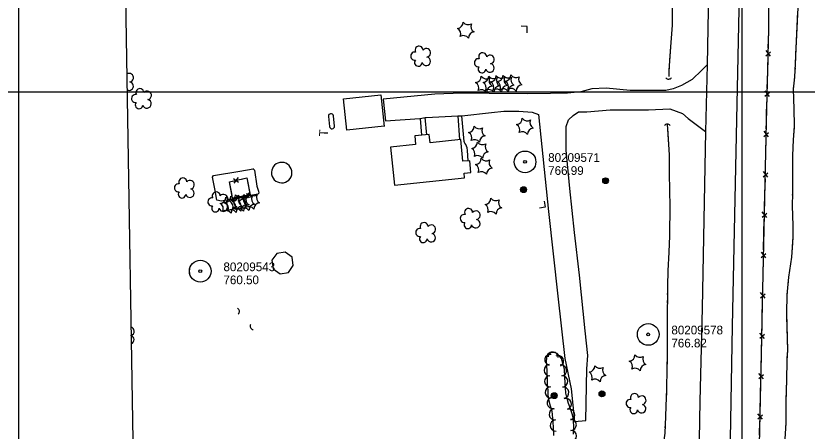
# Model space of a CAD drawing. Extents: x 591954 to 597000, y 198576 to 213500.
# Drawn here: x 593498 to 594045, y 207766 to 208052 of the extents above; entities that cross this region are included whole.
import ezdxf

# ---------------------------------------------------------------- set-up
doc = ezdxf.new("R2010")
doc.units = 0
for name, color, linetype in [('Level 10', 7, 'Continuous'), ('Level 11', 7, 'Continuous'), ('Level 12', 7, 'Continuous'), ('Level 14', 7, 'Continuous'), ('Level 15', 7, 'Continuous'), ('Level 17', 7, 'Continuous'), ('Level 18', 7, 'Continuous'), ('Level 19', 7, 'Continuous'), ('Level 4', 7, 'Continuous'), ('Level 6', 7, 'Continuous')]:
    doc.layers.add(name, color=color, linetype=linetype)

msp = doc.modelspace()

# ---------------------------------------------------------------- linework, layer by layer
at = {"layer": 'Level 10'}
for p, q in [((593500, 207500), (593500, 209000)), ((594000, 207500), (594000, 209000)), ((593000, 208000), (595000, 208000)), ((593500, 208000), (595000, 208000)), ((593500, 206500), (593500, 208000)), ((594000, 206500), (594000, 208000))]:
    msp.add_line(p, q, dxfattribs=at)
at = {"layer": 'Level 11'}
for points in [[(593991.47, 207734.14), (593993.19, 207838.07), (593996.52, 207991.65), (593997.85, 208056.88), (593999.78, 208160.44), (594001.38, 208238.17), (594003.22, 208352.61), (594005.03, 208445.65), (594007.61, 208557.14), (594009.01, 208631.52)], [(593983.86, 208434.05), (593979.64, 208220.43), (593977.27, 208106.99), (593975.66, 208018.56)], [(593975.66, 208018.56), (593974.67, 207972.6)], [(593974.67, 207972.6), (593972.17, 207850.51), (593970.68, 207786.4), (593969.83, 207733.19)]]:
    msp.add_lwpolyline(points, dxfattribs=at)
at = {"layer": 'Level 12'}
for p, q in [((593713.98, 207982.97), (593714.7, 207975.98)), ((593718.18, 207976.36), (593717.45, 207983.42))]:
    msp.add_line(p, q, dxfattribs=at)
for points in [[(593752.57, 207976.3), (593726.72, 207973.62), (593724.48, 207995.21), (593750.27, 207997.88), (593752.53, 207976.08), (593752.57, 207976.3)], [(593805.46, 207966.96), (593784.28, 207964.7), (593783.71, 207970.53), (593773.62, 207969.52), (593774.07, 207963.64), (593756.96, 207961.83), (593759.74, 207935.53), (593807.98, 207940.63), (593807.7, 207943.87), (593812.35, 207944.34), (593811.66, 207952.34), (593806.81, 207952.08), (593805.46, 207966.96)]]:
    msp.add_lwpolyline(points, dxfattribs=at)
for centre, radius, start, end in [((593715.73, 207983.13), 1.75, 9.4242, 185.4716), ((593716.44, 207976.18), 1.75, 186.6061, 5.8568), ((593681.71, 207944.2), 7.09, 99.9808, 279.9808), ((593681.71, 207944.2), 7.09, 279.9808, 99.9808)]:
    msp.add_arc(centre, radius, start, end, dxfattribs=at)
at = {"layer": 'Level 14'}
for centre, radius in [((593905.54, 207938.6), 2.02), ((593905.53, 207938.62), 1.52), ((593905.54, 207938.58), 1.01), ((593905.54, 207938.59), 0.502), ((593848.86, 207932.44), 2.02), ((593848.86, 207932.46), 1.52), ((593848.86, 207932.42), 1.01), ((593848.87, 207932.43), 0.502), ((593870.03, 207790.18), 2.02), ((593870.03, 207790.2), 1.52), ((593870.04, 207790.16), 1.01), ((593870.04, 207790.17), 0.502), ((593903.04, 207791.5), 2.02), ((593903.04, 207791.51), 1.52), ((593903.04, 207791.47), 1.01), ((593903.05, 207791.48), 0.502)]:
    msp.add_circle(centre, radius, dxfattribs=at)
at = {"layer": 'Level 15'}
for p, q in [((594016.36, 208024.89), (594019.61, 208027.6)), ((594019.6, 208024.63), (594016.46, 208028.43)), ((594015.63, 207997.04), (594018.88, 207999.75)), ((594018.86, 207996.78), (594015.73, 208000.58)), ((594014.99, 207969.17), (594018.21, 207971.91)), ((594018.23, 207968.94), (594015.05, 207972.71)), ((594014.47, 207941.33), (594017.72, 207944.04)), ((594017.71, 207941.07), (594014.57, 207944.87)), ((593648.39, 207940.08), (593651.82, 207937.61)), ((593648.95, 207936.89), (593651.85, 207940.87)), ((593660.93, 207927.99), (593657.43, 207929.61)), ((593659.4, 207930.9), (593658.36, 207926.64)), ((594013.76, 207913.47), (594016.99, 207916.19)), ((594016.99, 207913.23), (594013.84, 207917.02)), ((594013.15, 207885.62), (594016.38, 207888.34)), ((594016.38, 207885.38), (594013.23, 207889.16)), ((594015.78, 207857.52), (594012.62, 207861.31)), ((594012.54, 207857.76), (594015.77, 207860.49)), ((594012.05, 207829.9), (594015.27, 207832.64)), ((594015.28, 207829.68), (594012.11, 207833.45)), ((594011.44, 207802.06), (594014.68, 207804.78)), ((594014.68, 207801.81), (594011.53, 207805.6)), ((594010.77, 207774.21), (594014, 207776.92)), ((594014, 207773.96), (594010.85, 207777.75))]:
    msp.add_line(p, q, dxfattribs=at)
for points in [[(594011.53, 207735.03), (594011.82, 207755.98), (594013.38, 207819.77), (594013.94, 207853.22), (594015.3, 207915.54), (594016.14, 207947.64), (594016.65, 207978.84), (594018.35, 208043.38), (594018.66, 208075.6), (594019.71, 208108), (594020.69, 208140.16), (594021.26, 208172.72), (594021.85, 208204.16), (594023.2, 208300.18), (594024.4, 208341.93), (594025.15, 208374.64), (594026.12, 208406.89), (594026.68, 208438.14), (594027.63, 208471.43), (594027.92, 208503.97), (594028.66, 208536.16), (594029.23, 208568.68), (594029.81, 208600.39), (594030.79, 208634.01)], [(594018.3, 208041.41), (594018.35, 208043.38), (594018.43, 208051.37)], [(593851.38, 208040.62), (593851.25, 208045.12), (593847.3, 208045.21)], [(593851.38, 208040.62), (593851.25, 208045.12), (593847.3, 208045.21)], [(594018, 208030.1), (594018.3, 208041.41)], [(594017.57, 208013.56), (594017.83, 208023.52)], [(594017.27, 208002.24), (594017.57, 208013.56)], [(594016.83, 207985.71), (594017.1, 207995.67)], [(594016.58, 207974.39), (594016.65, 207978.84), (594016.83, 207985.71)], [(594016.31, 207957.86), (594016.47, 207967.81)], [(594016.11, 207946.54), (594016.14, 207947.64), (594016.31, 207957.86)], [(593657.64, 207940.66), (593659.88, 207928.85), (593647.73, 207926.46), (593645.69, 207937.93), (593657.64, 207940.66)], [(593647.13, 207929.88), (593645.69, 207937.93), (593647.43, 207938.32)], [(593653.84, 207939.79), (593657.64, 207940.66)], [(593657.64, 207940.66), (593659.49, 207930.88)], [(594015.68, 207930.01), (594015.94, 207939.96)], [(593655.44, 207927.98), (593647.73, 207926.46), (593647.13, 207929.88)], [(594015.39, 207918.69), (594015.68, 207930.01)], [(593863.16, 207924.51), (593863.89, 207920.23), (593859.88, 207919.76)], [(593863.16, 207924.51), (593863.89, 207920.23), (593859.88, 207919.76)], [(594015.01, 207902.15), (594015.23, 207912.11)], [(594014.76, 207890.83), (594015.01, 207902.15)], [(594014.4, 207874.3), (594014.62, 207884.25)], [(594014.16, 207862.98), (594014.4, 207874.3)], [(594013.83, 207846.45), (594013.94, 207853.22), (594014.01, 207856.4)], [(594013.64, 207835.13), (594013.83, 207846.45)], [(594013.35, 207818.59), (594013.38, 207819.77), (594013.53, 207828.55)], [(594013.07, 207807.27), (594013.35, 207818.59)], [(594012.67, 207790.74), (594012.91, 207800.69)], [(594012.39, 207779.42), (594012.67, 207790.74)], [(594011.99, 207762.89), (594012.23, 207772.84)]]:
    msp.add_lwpolyline(points, dxfattribs=at)
for centre, start, end in [((593949.12, 208011.26), 219.1794, 325.419), ((593948.23, 207975.16), 38.4794, 144.719), ((593649.95, 207848.31), 315.3794, 61.619), ((593662.42, 207838.24), 152.0794, 258.319)]:
    msp.add_arc(centre, 2.5, start, end, dxfattribs=at)
at = {"layer": 'Level 17'}
for points in [[(593975.66, 208018.56), (593972.02, 208015.05), (593965.37, 208008.55), (593958.02, 208004.35), (593952.25, 208001.94), (593947.15, 208000.98), (593937.57, 208000.96), (593922.56, 208000.81), (593905.84, 208002.62), (593895.92, 208002.11), (593888.35, 207999.97), (593879.11, 207999.04), (593867.49, 207998.8), (593851.82, 207998.71), (593825.15, 207998.79), (593806.45, 207999.07), (593787.45, 207998.3), (593751.83, 207995.01), (593753.47, 207979.92), (593777.09, 207981.63), (593777.38, 207981.67)], [(593806.18, 207983.38), (593826.78, 207985.75), (593835.28, 207986.54), (593845.59, 207986.69), (593854.83, 207986.03), (593859.15, 207984.41), (593866.1, 207917.43), (593872.44, 207858.96), (593877.29, 207815.88), (593881.65, 207794.83), (593884.04, 207772.26), (593891.79, 207773.01), (593892.65, 207808.64), (593893.31, 207817.88), (593891.53, 207834.95), (593887.44, 207873.28), (593884.06, 207902.84), (593880.73, 207933.24), (593878.38, 207959.76), (593878.25, 207975.99), (593879.94, 207980.59), (593883.23, 207983.7), (593886.84, 207986.08), (593892.46, 207986.23), (593908.62, 207987.58), (593935.19, 207987.58), (593949.89, 207988.19), (593958.72, 207984.96), (593962.68, 207981.54), (593974.67, 207972.6)], [(593777.38, 207981.67), (593780.86, 207982.16)], [(593777.38, 207981.67), (593778.4, 207970)], [(593780.86, 207982.16), (593781.65, 207982.28), (593803.41, 207983.31)], [(593782.05, 207970.36), (593780.86, 207982.16)], [(593803.41, 207983.31), (593803.74, 207983.33), (593806.18, 207983.38)], [(593803.41, 207983.31), (593804.6, 207966.86)], [(593810.6, 207952.29), (593809.99, 207959.5), (593809.77, 207961.41), (593809.42, 207962.42), (593808.91, 207963.55), (593808.25, 207964.52), (593807.92, 207965.09), (593807.72, 207965.79), (593806.18, 207983.38)], [(593661.82, 207946.93), (593662.8, 207945.82), (593664.63, 207934.88), (593665.71, 207931.3), (593665.88, 207930.05), (593665.25, 207929.3), (593640.13, 207924.43), (593636.86, 207925.2), (593635.62, 207931.88), (593633.99, 207941.05), (593634.48, 207942.12), (593652.84, 207945.2), (593661.96, 207946.8)], [(593688.82, 207885.92), (593684.07, 207889.23), (593678.26, 207888.24), (593674.96, 207883.8), (593675.91, 207877.8), (593680.56, 207874.26), (593686.51, 207875.2), (593689.55, 207879.98), (593688.82, 207885.92)]]:
    msp.add_lwpolyline(points, dxfattribs=at)
at = {"layer": 'Level 18'}
for points in [[(593883.46, 207773.89), (593882.71, 207776.9), (593881.97, 207779.06), (593880.83, 207782.51), (593879.99, 207784.76), (593878.94, 207788.12), (593878.05, 207791.96), (593877.79, 207795.61), (593877.59, 207798.88), (593877.33, 207803.09), (593877.15, 207808.57), (593874.97, 207815.81), (593872.08, 207819.34), (593870.65, 207819.87), (593867.27, 207819.9), (593865.42, 207818.52), (593864.79, 207816.65), (593864.55, 207813.59), (593864.66, 207810.87), (593864.88, 207807.22), (593865.27, 207798.42), (593865.52, 207793.56), (593865.69, 207790.8), (593866.12, 207787.45), (593867.27, 207783.24), (593868.3, 207779.41), (593868.57, 207777.13), (593869.04, 207771.66), (593869.24, 207768.34), (593869.59, 207762.64)], [(593883.43, 207763.52), (593883.66, 207767.52), (593883.46, 207773.89)]]:
    msp.add_lwpolyline(points, dxfattribs=at)
for centre, radius, start, end in [((593802.81, 208048.08), 4.3, 275.2113, 0.9762), ((593810.63, 208050.63), 4.3, 215.2113, 300.9762), ((593816.75, 208045.14), 4.3, 155.2113, 240.9762), ((593801.12, 208040.04), 4.3, 335.2113, 60.9762), ((593815.05, 208037.1), 4.3, 95.2113, 180.9762), ((593807.23, 208034.55), 4.3, 35.2113, 120.9762), ((593776.63, 208028.77), 2.78, 1.3946, 209.1675), ((593773.63, 208024.7), 2.78, 78.0716, 279.0826), ((593781.68, 208026.92), 2.97, 278.4237, 139.6575), ((593820.61, 208024.17), 2.78, 1.3946, 209.1675), ((593825.65, 208022.32), 2.97, 278.4237, 139.6575), ((593776.1, 208020.3), 2.61, 140.7797, 358.7123), ((593781.57, 208021.06), 2.97, 196.0745, 79.0477), ((593817.61, 208020.1), 2.78, 78.0716, 279.0826), ((593820.07, 208015.7), 2.61, 140.7797, 358.7123), ((593825.54, 208016.46), 2.97, 196.0745, 79.0477), ((593576.34, 208009.76), 2.97, 278.4237, 126.9542), ((593815.34, 208010.68), 4.3, 275.2113, 0.9762), ((593823.16, 208013.23), 4.3, 215.2113, 300.9762), ((593820.45, 208010.8), 4.3, 275.2113, 0.9762), ((593828.27, 208013.35), 4.3, 215.2113, 300.9762), ((593829.28, 208007.74), 4.3, 155.2113, 240.9762), ((593825.69, 208011.07), 4.3, 275.2113, 0.9762), ((593833.51, 208013.62), 4.3, 215.2113, 300.9762), ((593834.39, 208007.86), 4.3, 155.2113, 240.9762), ((593830.37, 208011.3), 4.3, 275.2113, 0.9762), ((593838.19, 208013.85), 4.3, 215.2113, 300.9762), ((593839.63, 208008.13), 4.3, 155.2113, 240.9762), ((593835.8, 208011.53), 4.3, 275.2113, 0.9762), ((593844.31, 208008.36), 4.3, 155.2113, 240.9762), ((593843.62, 208014.09), 4.3, 215.2113, 300.9762), ((593849.74, 208008.6), 4.3, 155.2113, 240.9762), ((593576.23, 208003.91), 2.97, 239.7655, 79.0477), ((593813.65, 208002.63), 4.3, 335.2113, 60.9762), ((593818.76, 208002.75), 4.3, 335.2113, 60.9762), ((593827.58, 207999.7), 4.3, 95.2113, 180.9762), ((593824, 208003.02), 4.3, 335.2113, 60.9762), ((593832.69, 207999.82), 4.3, 95.2113, 180.9762), ((593828.68, 208003.26), 4.3, 335.2113, 60.9762), ((593837.93, 208000.08), 4.3, 95.2113, 180.9762), ((593834.11, 208003.49), 4.3, 335.2113, 60.9762), ((593842.61, 208000.32), 4.3, 95.2113, 180.9762), ((593848.04, 208000.55), 4.3, 95.2113, 180.9762), ((593580.67, 207995.33), 2.78, 78.0716, 279.0826), ((593583.67, 207999.41), 2.78, 1.3946, 209.1675), ((593588.71, 207997.55), 2.97, 278.4237, 139.6575), ((593819.77, 207997.14), 4.3, 35.2113, 120.9762), ((593824.87, 207997.26), 4.3, 35.2113, 120.9762), ((593830.12, 207997.53), 4.3, 35.2113, 120.9762), ((593834.79, 207997.77), 4.3, 35.2113, 120.9762), ((593840.23, 207998), 4.3, 35.2113, 120.9762), ((593583.13, 207990.93), 2.61, 140.7797, 358.7123), ((593588.6, 207991.7), 2.97, 196.0745, 79.0477), ((593843.66, 207981.69), 4.3, 275.2113, 0.9762), ((593851.47, 207984.24), 4.3, 215.2113, 300.9762), ((593810.43, 207976.21), 4.3, 275.2113, 0.9762), ((593818.24, 207978.77), 4.3, 215.2113, 300.9762), ((593841.96, 207973.64), 4.3, 335.2113, 60.9762), ((593857.59, 207978.75), 4.3, 155.2113, 240.9762), ((593808.73, 207968.17), 4.3, 335.2113, 60.9762), ((593824.36, 207973.27), 4.3, 155.2113, 240.9762), ((593848.08, 207968.15), 4.3, 35.2113, 120.9762), ((593855.89, 207970.71), 4.3, 95.2113, 180.9762), ((593814.85, 207962.68), 4.3, 35.2113, 120.9762), ((593812.64, 207965.22), 4.3, 275.2113, 0.9762), ((593820.45, 207967.77), 4.3, 215.2113, 300.9762), ((593822.66, 207965.23), 4.3, 95.2113, 180.9762), ((593810.94, 207957.18), 4.3, 335.2113, 60.9762), ((593826.57, 207962.28), 4.3, 155.2113, 240.9762), ((593817.06, 207951.69), 4.3, 35.2113, 120.9762), ((593815.33, 207954.07), 4.3, 275.2113, 0.9762), ((593823.14, 207956.63), 4.3, 215.2113, 300.9762), ((593824.88, 207954.24), 4.3, 95.2113, 180.9762), ((593813.63, 207946.03), 4.3, 335.2113, 60.9762), ((593829.26, 207951.13), 4.3, 155.2113, 240.9762), ((593819.75, 207940.54), 4.3, 35.2113, 120.9762), ((593827.57, 207943.09), 4.3, 95.2113, 180.9762), ((593613.33, 207937.74), 2.78, 1.3946, 209.1675), ((593618.37, 207935.88), 2.97, 278.4237, 139.6575), ((593610.33, 207933.66), 2.78, 78.0716, 279.0826), ((593618.26, 207930.03), 2.97, 196.0745, 79.0477), ((593612.79, 207929.26), 2.61, 140.7797, 358.7123), ((593633.45, 207924.02), 2.78, 78.0716, 279.0826), ((593636.45, 207928.1), 2.78, 1.3946, 209.1675), ((593638.74, 207927.22), 4.3, 275.2113, 0.9762), ((593641.49, 207926.24), 2.97, 278.4237, 139.6575), ((593642.29, 207927.81), 4.3, 275.2113, 0.9762), ((593646.56, 207929.77), 4.3, 215.2113, 300.9762), ((593645.47, 207928.74), 4.3, 275.2113, 0.9762), ((593650.11, 207930.36), 4.3, 215.2113, 300.9762), ((593647.32, 207928.57), 4.3, 275.2113, 0.9762), ((593653.28, 207931.3), 4.3, 215.2113, 300.9762), ((593651.15, 207929.05), 4.3, 275.2113, 0.9762), ((593655.13, 207931.12), 4.3, 215.2113, 300.9762), ((593656.23, 207924.87), 4.3, 155.2113, 240.9762), ((593654.56, 207929.95), 4.3, 275.2113, 0.9762), ((593659.4, 207925.81), 4.3, 155.2113, 240.9762), ((593658.96, 207931.6), 4.3, 215.2113, 300.9762), ((593661.25, 207925.63), 4.3, 155.2113, 240.9762), ((593662.37, 207932.51), 4.3, 215.2113, 300.9762), ((593665.08, 207926.11), 4.3, 155.2113, 240.9762), ((593668.49, 207927.01), 4.3, 155.2113, 240.9762), ((593821.87, 207926.54), 4.3, 275.2113, 0.9762), ((593829.68, 207929.09), 4.3, 215.2113, 300.9762), ((593635.91, 207919.63), 2.61, 140.7797, 358.7123), ((593641.38, 207920.39), 2.97, 196.0745, 79.0477), ((593637.05, 207919.17), 4.3, 335.2113, 60.9762), ((593640.6, 207919.76), 4.3, 335.2113, 60.9762), ((593643.77, 207920.7), 4.3, 335.2113, 60.9762), ((593645.62, 207920.52), 4.3, 335.2113, 60.9762), ((593652.68, 207924.28), 4.3, 155.2113, 240.9762), ((593654.53, 207916.82), 4.3, 95.2113, 180.9762), ((593649.45, 207921), 4.3, 335.2113, 60.9762), ((593657.71, 207917.76), 4.3, 95.2113, 180.9762), ((593652.86, 207921.91), 4.3, 335.2113, 60.9762), ((593659.55, 207917.59), 4.3, 95.2113, 180.9762), ((593663.39, 207918.07), 4.3, 95.2113, 180.9762), ((593666.79, 207918.97), 4.3, 95.2113, 180.9762), ((593820.17, 207918.5), 4.3, 335.2113, 60.9762), ((593835.8, 207923.6), 4.3, 155.2113, 240.9762), ((593643.16, 207913.68), 4.3, 35.2113, 120.9762), ((593646.72, 207914.27), 4.3, 35.2113, 120.9762), ((593650.98, 207916.24), 4.3, 95.2113, 180.9762), ((593649.89, 207915.21), 4.3, 35.2113, 120.9762), ((593651.74, 207915.03), 4.3, 35.2113, 120.9762), ((593655.57, 207915.51), 4.3, 35.2113, 120.9762), ((593658.98, 207916.42), 4.3, 35.2113, 120.9762), ((593810.89, 207916.64), 2.78, 1.3946, 209.1675), ((593815.93, 207914.79), 2.97, 278.4237, 139.6575), ((593826.29, 207913), 4.3, 35.2113, 120.9762), ((593834.11, 207915.56), 4.3, 95.2113, 180.9762), ((593807.89, 207912.57), 2.78, 78.0716, 279.0826), ((593815.82, 207908.93), 2.97, 196.0745, 79.0477), ((593777.08, 207902.87), 2.78, 78.0716, 279.0826), ((593780.08, 207906.95), 2.78, 1.3946, 209.1675), ((593785.12, 207905.09), 2.97, 278.4237, 139.6575), ((593810.35, 207908.17), 2.61, 140.7797, 358.7123), ((593779.54, 207898.47), 2.61, 140.7797, 358.7123), ((593785.01, 207899.24), 2.97, 196.0745, 79.0477), ((593576.84, 207834.72), 2.97, 283.5293, 78.3666), ((593576.73, 207828.87), 2.97, 287.6659, 74.23), ((593867.21, 207814.89), 3.74, 79.9388, 259.9235), ((593869.26, 207816.87), 3.45, 356.1334, 176.118), ((593872.75, 207814.16), 3.79, 296.6166, 116.6013), ((593921.55, 207818.35), 4.3, 275.2113, 0.9762), ((593929.36, 207820.9), 4.3, 215.2113, 300.9762), ((593935.48, 207815.41), 4.3, 155.2113, 240.9762), ((593866.85, 207807.8), 3.87, 92.9589, 272.9436), ((593919.85, 207810.31), 4.3, 335.2113, 60.9762), ((593933.79, 207807.37), 4.3, 95.2113, 180.9762), ((593874.77, 207807.58), 3.84, 278.1177, 98.1024), ((593893.75, 207810.81), 4.3, 275.2113, 0.9762), ((593892.05, 207802.77), 4.3, 335.2113, 60.9762), ((593901.56, 207813.36), 4.3, 215.2113, 300.9762), ((593907.68, 207807.87), 4.3, 155.2113, 240.9762), ((593925.97, 207804.82), 4.3, 35.2113, 120.9762), ((593867.23, 207800.06), 3.87, 92.6543, 272.639), ((593875.5, 207800.09), 3.87, 273.2705, 93.2552), ((593898.17, 207797.28), 4.3, 35.2113, 120.9762), ((593905.99, 207799.83), 4.3, 95.2113, 180.9762), ((593867.71, 207792.42), 3.86, 94.5133, 274.498), ((593876.27, 207792.26), 3.85, 277.9349, 97.9195), ((593925.49, 207788.88), 2.78, 1.3946, 209.1675), ((593930.53, 207787.02), 2.97, 278.4237, 139.6575), ((593868.9, 207785.16), 3.86, 104.195, 284.1797), ((593878.08, 207784.42), 3.86, 288.1261, 108.1107), ((593922.49, 207784.8), 2.78, 78.0716, 279.0826), ((593870.4, 207777.36), 3.86, 97.5758, 277.5605), ((593880.39, 207777.09), 3.86, 286.7936, 106.7783), ((593924.95, 207780.4), 2.61, 140.7797, 358.7123), ((593930.42, 207781.17), 2.97, 196.0745, 79.0477), ((593871.18, 207769.55), 3.87, 93.7532, 273.7379), ((593881.52, 207770.04), 3.82, 270.9376, 90.9223), ((593881.61, 207762.37), 3.86, 270.7275, 90.7122)]:
    msp.add_arc(centre, radius, start, end, dxfattribs=at)
at = {"layer": 'Level 19'}
for points in [[(593950.31, 208079.83), (593950.68, 208071.71), (593951.49, 208057.59), (593951.51, 208050.86)], [(594029.42, 207756.55), (594030.25, 207771.47), (594030.31, 207785.42), (594030.77, 207801.07), (594031.01, 207814.18), (594031.55, 207821.58), (594030.77, 207847.07), (594031.08, 207859.86), (594032.22, 207872.03), (594034.17, 207885.71), (594035.14, 207899.9), (594035.1, 207907.64), (594034.71, 207921.18), (594034.84, 207929.92), (594034.95, 207956.12), (594035.39, 207966.75), (594036.06, 207976.55), (594035.92, 207988.33), (594035.44, 208001.72), (594036.3, 208010.13), (594036.85, 208019.6), (594037.13, 208029.8), (594038.51, 208058.32)], [(593951.49, 208057.59), (593951.53, 208045.9), (593950.7, 208033.98), (593949.74, 208021.06), (593949.28, 208014.84), (593949.16, 208010.46)], [(594037.04, 208026.43), (594037.13, 208029.8), (594038.37, 208055.4)], [(593951.51, 208050.86), (593951.53, 208045.9), (593950.7, 208033.98), (593949.81, 208021.92)], [(594036.87, 208020.44), (594036.93, 208022.43)], [(593949.51, 208017.93), (593949.36, 208015.94)], [(594036.55, 208014.45), (594036.67, 208016.44)], [(593949.2, 208011.94), (593949.16, 208010.46)], [(594036.12, 208008.46), (594036.3, 208010.13), (594036.31, 208010.45)], [(594035.99, 207975.51), (594036.06, 207976.55), (594035.92, 207988.33), (594035.44, 208001.72), (594035.72, 208004.48)], [(593948.18, 207977.66), (593949.46, 207956.41), (593949.46, 207945.92)], [(593948.35, 207974.89), (593949.46, 207956.41), (593949.46, 207944.82), (593949.72, 207931.04), (593949.86, 207921.8), (593949.79, 207900.39), (593949.19, 207889.19), (593948.56, 207876.29), (593948.24, 207866.13), (593948.09, 207840.54), (593948.04, 207828.9), (593948.1, 207818.58), (593947.85, 207808.61), (593947.59, 207794.98), (593947.24, 207782.9), (593946.92, 207775.75), (593946.43, 207764.36), (593945.67, 207757.6), (593944.73, 207750.6), (593944.37, 207744.8), (593944.44, 207742.13), (593944.55, 207732.07)], [(594034.91, 207946.54), (594034.95, 207956.12), (594035.39, 207966.75), (594035.99, 207975.51)], [(593949.51, 207941.92), (593949.55, 207939.92)], [(594034.88, 207940.54), (594034.89, 207942.54)], [(593949.63, 207935.92), (593949.67, 207933.92)], [(594034.86, 207934.54), (594034.86, 207936.54)], [(593949.74, 207929.92), (593949.77, 207927.92)], [(594034.82, 207928.54), (594034.84, 207929.92), (594034.84, 207930.54)], [(593949.83, 207923.92), (593949.86, 207921.8), (593949.79, 207900.39), (593949.5, 207894.93)], [(594034.84, 207895.55), (594035.14, 207899.9), (594035.1, 207907.64), (594034.71, 207921.18), (594034.76, 207924.54)], [(593949.5, 207894.93), (593949.19, 207889.19), (593948.56, 207876.29), (593948.24, 207866.13), (593948.23, 207865.96)], [(594031.72, 207866.74), (594032.22, 207872.03), (594034.17, 207885.71), (594034.84, 207895.55)], [(593948.21, 207861.96), (593948.2, 207859.96)], [(594031.16, 207860.77), (594031.35, 207862.76)], [(593948.18, 207855.96), (593948.17, 207853.96)], [(594030.96, 207854.77), (594031, 207856.77)], [(593948.14, 207849.96), (593948.13, 207847.96)], [(594030.81, 207848.77), (594030.86, 207850.77)], [(594031.13, 207815.8), (594031.55, 207821.58), (594030.84, 207844.77)], [(593948.11, 207843.96), (593948.09, 207840.54), (593948.04, 207828.9), (593948.1, 207818.58), (593948.01, 207814.96)], [(593948.01, 207814.96), (593947.85, 207808.61), (593947.59, 207794.98), (593947.33, 207785.97)], [(594030.35, 207786.81), (594030.77, 207801.07), (594031.01, 207814.18), (594031.13, 207815.8)], [(593947.2, 207781.97), (593947.11, 207779.97)], [(594030.29, 207780.81), (594030.3, 207782.81)], [(593946.93, 207775.98), (593946.92, 207775.75), (593946.85, 207773.98)], [(594030.27, 207774.81), (594030.27, 207776.81)], [(593946.68, 207769.98), (593946.59, 207767.98)], [(594030.1, 207768.82), (594030.22, 207770.82)]]:
    msp.add_lwpolyline(points, dxfattribs=at)
at = {"layer": 'Level 4'}
msp.add_lwpolyline([(593564.2, 208601.21), (593566.78, 208481.65), (593580.11, 207675.93)], dxfattribs=at)
at = {"layer": 'Level 6'}
for centre, radius in [((593849.85, 207951.62), 7.5), ((593849.86, 207951.62), 7.5), ((593849.85, 207951.62), 0.96), ((593849.86, 207951.62), 0.96), ((593625.44, 207876.14), 7.5), ((593625.45, 207876.14), 7.5), ((593625.44, 207876.14), 0.96), ((593625.45, 207876.14), 0.96), ((593935, 207832.5), 7.5), ((593935, 207832.5), 7.5), ((593935, 207832.5), 0.96), ((593935, 207832.5), 0.96)]:
    msp.add_circle(centre, radius, dxfattribs=at)

# ---------------------------------------------------------------- texts
at = {"layer": 'Level 12'}
msp.add_text('T', height=6, rotation=88.8567, dxfattribs=at).set_placement((593713.55, 207969.08))
at = {"layer": 'Level 6'}
for s, p in [('80209571', (593865.85, 207951.62)), ('80209571', (593865.86, 207951.62)), ('766.99', (593865.85, 207942.62)), ('766.99', (593865.86, 207942.62)), ('80209543', (593641.44, 207876.14)), ('80209543', (593641.45, 207876.14)), ('760.50', (593641.44, 207867.14)), ('760.50', (593641.45, 207867.14)), ('80209578', (593950.99, 207832.5)), ('80209578', (593951, 207832.5)), ('766.82', (593950.99, 207823.5)), ('766.82', (593951, 207823.5))]:
    msp.add_text(s, height=6, dxfattribs=at).set_placement(p)

doc.saveas('drawing.dxf')
